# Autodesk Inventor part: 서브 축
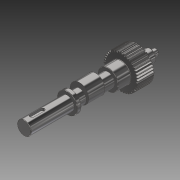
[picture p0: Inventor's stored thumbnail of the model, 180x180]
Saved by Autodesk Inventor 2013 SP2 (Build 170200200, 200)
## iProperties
Created: 2016-02
Part Number: 서브 축
Material: 강철, 연강
Document SubType Name: Modeling
Designer: mdu
Categories: <?xml version="1.0" encoding="UTF-16"?> <MemberInstance><Categories><FamilyTemplate><FamilyTemplateParameter ValueType="xs:double" Id="1" ObjectReferenceKey="da
Density: 7.86 g/cm^3
Mass: 506.173 g
Surface Area: 164.116 cm^2
Volume: 64.3986 cm^3
CustomPartVersion: 1
Author: mdu
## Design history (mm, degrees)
sketch "Sketch1"
  geometry: C1 r 21 at (0, 0)
  constraints: 1 centre point
  dimensions: "d0" = 42 diameter of C1 (= da_da)
extrude "Extrusion1" new body sketch "Sketch1" distance "d1" = 20 (= da_b); taper "d2" = 0 deg
workplane "Work Plane2"
feature "피치 지름" dims "d4" = 10, "d5" = 0
workplane "Work Plane8"
workplane "Work Plane9"
chamfer "모따기1" distance "d49" = 0.2; stored, may be unused: second distance "d50" = 2, angle "d51" = 45 deg
sketch "스케치3"
  geometry: C1 r 12.5 at (0, 0); 1 further point
  constraints: 1 centre point, 1 coincident
  dimensions: "d52" = 25 diameter of C1
extrude "돌출2" join sketch "스케치3" distance "d53" = 16; taper "d54" = 0 deg
sketch "스케치4"
  geometry: C1 r 8.5 at (0, 0); 1 further point
  constraints: 1 centre point, 1 coincident
  dimensions: "d55" = 17 diameter of C1
extrude "돌출3" join sketch "스케치4" distance "d56" = 103; taper "d57" = 0 deg
sketch "스케치5"
  geometry: C1 r 7.5 at (0, 0); 1 further point
  constraints: 1 centre point, 1 coincident
  dimensions: "d62" = 15 diameter of C1
extrude "돌출4" join sketch "스케치5" distance "d63" = 16; taper "d64" = 0 deg
sketch "스케치6"
  geometry: C1 r 4 at (0, 0); 1 further point
  constraints: 1 centre point, 1 coincident
  dimensions: "d65" = 8 diameter of C1
extrude "돌출5" join sketch "스케치6" distance "d66" = 7; taper "d67" = 0 deg
chamfer "모따기2" distance "d58" = 0.5; stored, may be unused: second distance "d59" = 2, angle "d60" = 45 deg
fillet "모깎기1" dims "d61" = 0.5
feature "스퍼 기어" dims "da_b" = 20, "da_d" = 40, "da_aw" = 31, "da_da" = 42, "da_df" = 37.5, "da_dw" = 40, angle "da_beta" = 0 deg, "da_lefttooth" = 0, "da_righttooth" = 0
node "작업 평면11"
sketch "스케치7"
  geometry: C1 r 8.5 at (0, 0) reference; C2 r 11.5 at (0, 3); 1 further point
  constraints: 1 centre point, 1 tangent, 1 vertical alignment
  dimensions: "d71" = 3 distance of C2.centre point (0, 0); "d72" = 23 diameter of C2 (derived)
extrude "돌출6" join sketch "스케치7" stored distance "d73" = 20; taper "d74" = 0 deg
node "작업 평면12"
sketch "스케치8"
  geometry: C1 r 12.5 at (0, 0) reference; 1 further point
extrude "돌출7" join sketch "스케치8" distance "d76" = 5; taper "d77" = 0 deg
chamfer "모따기3" distance "d78" = 0.5; stored, may be unused: second distance "d79" = 2, angle "d80" = 45 deg
sketch "스케치9"
  geometry: L1 (-8.5, 86)-(-8.5, 138.5) reference; L2 (-8, 139)-(8, 139) reference; L3 (0, 0)-(0, 139); L4 (-8.5, 115)-(0, 115); L5 (-8.5, 115)-(-8.5, 113.5); L6 (-7, 115)-(-8.5, 113.5)
  constraints: 8 end point, 4 point on line, 1 midpoint, 1 perpendicular
  dimensions: "d81" = 24 distance between parallel lines of L2 L4; "d82" = 45 deg angle of L6 L5; "d83" = 3 diameter of L5.end L4
revolve "회전1" sketch "스케치9" stored, may be unused: angle "d84" = 90 deg
sketch "스케치10"
  geometry: L1 (-8.5, 113.5)-(-7, 115) reference; L2 (-8.5, 116.5)-(-7, 115) reference; 2 further points
  constraints: 1 coincident
node "작업점1"
node "작업 평면14"
sketch "스케치11"
  geometry: L1 (8.5, 102.5)-(-8.5, 102.5) reference; L2 (0, 102.5)-(0, -36); L3 (-2.5, 93.5)-(-2.5, 80.5); L4 (2.5, 80.5)-(2.5, 93.5); L5 (-8, 103)-(8, 103) reference; A1 r 2.5 centre (0, 93.5) between (2.5, 93.5) and (-2.5, 93.5); A2 r 2.5 centre (0, 80.5) between (-2.5, 80.5) and (2.5, 80.5)
  constraints: 6 end point, 4 point on circle, 4 tangent, 2 centre point, 1 midpoint, 1 parallel, 1 perpendicular, 1 point on line, 1 vertical alignment
  dimensions: "d85" = 7 distance edge to line of A1 L5; "d86" = 18 dimension on A2 A1; "d87" = 5 distance between parallel lines of L3 L4
extrude "돌출8" cut sketch "스케치11" distance "d88" = 3; taper "d89" = 0 deg
body "Solid1"
sketch "Sketch2"
  geometry: C1 r 21 at (0, 0) reference; C2 r 20 at (0, 0)
  constraints: 1 centre point, 1 coincident
  dimensions: "d3" = 40 diameter of C2 (= da_dw)
body "Srf1"
other parameters: "d16" = 31 (= da_aw), "d17" = 0, "d34" = 4.5 deg (computed from da_z), "d39" = 0, "d41" = 0, "d43" = 31 (= da_aw), "d46" = 31 (= da_aw), "d47" = 0, "d48" = 0, "d68" = 25
